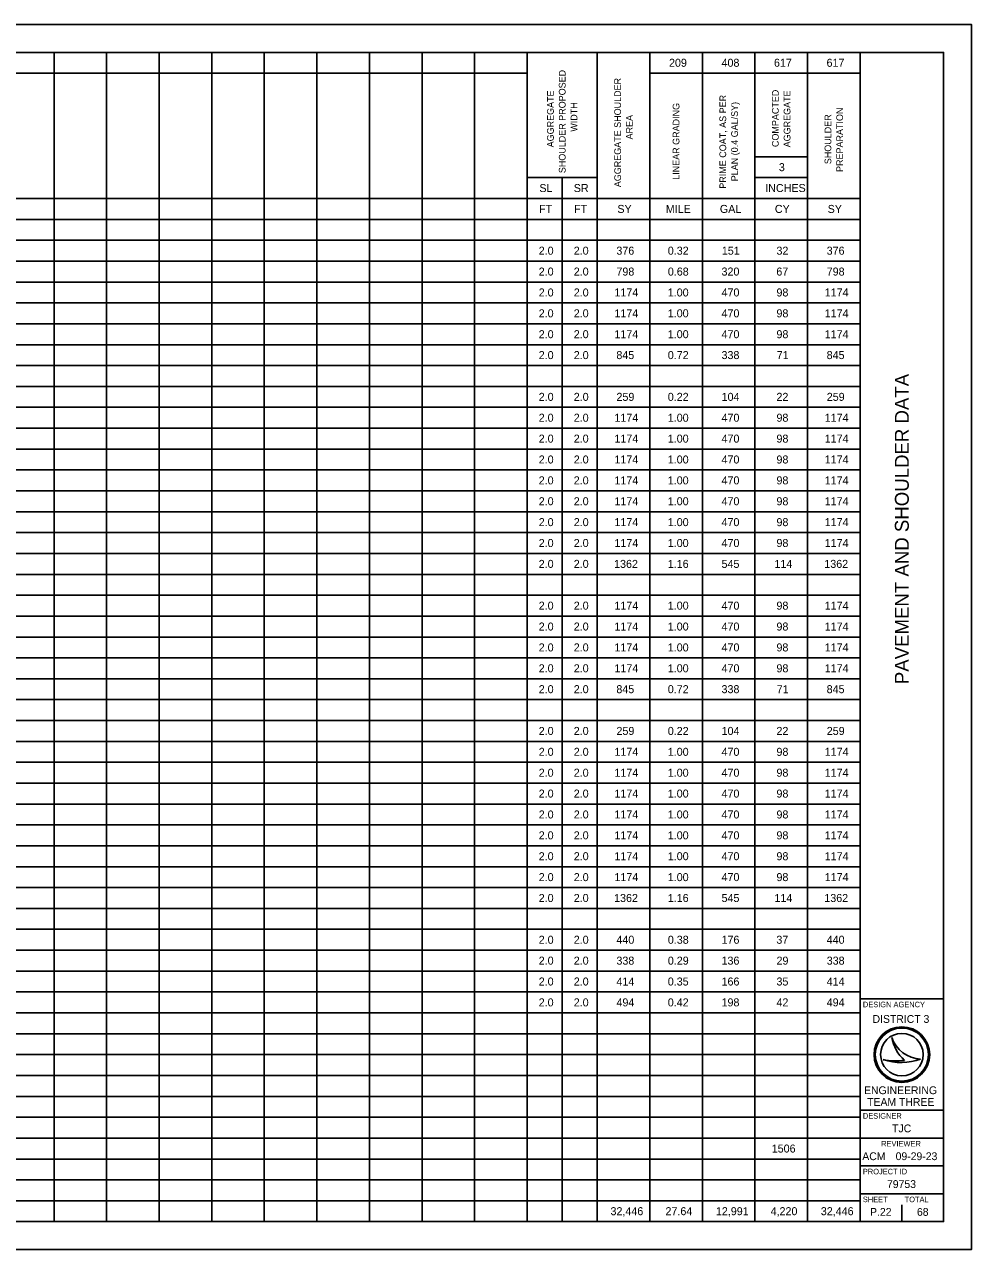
# Model space of a CAD drawing. Extents: x 0 to 34, y 0 to 22.
# Drawn here: x 17 to 34, y 0 to 22 of the extents above; entities that cross this region are included whole.
import ezdxf

# ---------------------------------------------------------------- set-up
doc = ezdxf.new("R2010")
doc.units = 0
for name, color, linetype in [('SH_Border', 7, 'Continuous'), ('SH_Cut_Line', 7, 'Continuous'), ('SH_Data', 7, 'Continuous'), ('SH_Text', 7, 'Continuous')]:
    doc.layers.add(name, color=color, linetype=linetype)

msp = doc.modelspace()

# ---------------------------------------------------------------- linework, layer by layer
at = {"layer": 'SH_Border'}
for p, q in [((32, 0.5), (32, 21.5)), ((32, 4.5), (33.5, 4.5)), ((32, 2.5), (33.5, 2.5)), ((32, 2), (33.5, 2)), ((32, 1.5), (33.5, 1.5)), ((32, 1), (33.5, 1))]:
    msp.add_line(p, q, dxfattribs=at)
msp.add_lwpolyline([(1.5, 21.5), (33.5, 21.5), (33.5, 0.5), (1.5, 0.5)], close=True, dxfattribs=at)
at = {"layer": 'SH_Cut_Line'}
msp.add_lwpolyline([(0, 0), (34, 0), (34, 22), (0, 22)], close=True, dxfattribs=at)
at = {"layer": 'SH_Data'}
for p, q in [((32.567, 3.81), (32.567, 3.81)), ((32.417, 3.41), (32.417, 3.41)), ((32.75, 3.5), (32.75, 3.5)), ((33.087, 3.419), (33.087, 3.419)), ((32.375, 0.675), (32.375, 0.675)), ((32.75, 0.5), (32.75, 0.8))]:
    msp.add_line(p, q, dxfattribs=at)
for radius in [0.5, 0.477, 0.477, 0.382]:
    msp.add_circle((32.75, 3.5), radius, dxfattribs=at)
for centre, radius, start, end in [((33.116, 3.998), 0.58, 198.9257, 198.9319), ((33.347, 3.97), 0.796, 191.6379, 191.6421), ((33.116, 3.998), 0.58, 198.9319, 267.1657), ((33.347, 3.97), 0.796, 191.6421, 226.0947), ((32.739, 4.37), 1.013, 251.4576, 290.0832), ((32.648, 4.654), 1.266, 259.4964, 259.4995), ((32.739, 4.37), 1.013, 251.4527, 251.4576), ((32.648, 4.654), 1.266, 259.4995, 276.6672)]:
    msp.add_arc(centre, radius, start, end, dxfattribs=at)
at = {"layer": 'SH_Text'}
for p, q in [((1.5, 21.5), (32, 21.5)), ((17.53, 21.5), (17.53, 0.5)), ((18.474, 21.5), (18.474, 0.5)), ((19.417, 21.5), (19.417, 0.5)), ((20.361, 21.5), (20.361, 0.5)), ((21.305, 21.5), (21.305, 0.5)), ((22.248, 21.5), (22.248, 0.5)), ((23.192, 21.5), (23.192, 0.5)), ((24.136, 21.5), (24.136, 0.5)), ((25.08, 21.5), (25.08, 0.5)), ((26.023, 21.5), (26.023, 0.5)), ((27.281, 21.5), (27.281, 0.5)), ((28.225, 21.5), (28.225, 0.5)), ((29.169, 21.5), (29.169, 0.5)), ((30.113, 21.5), (30.113, 0.5)), ((31.056, 21.5), (31.056, 0.5)), ((32, 21.5), (32, 0.5)), ((10.164, 21.125), (26.023, 21.125)), ((28.225, 21.125), (32, 21.125)), ((30.113, 19.625), (31.056, 19.625)), ((26.023, 19.25), (27.281, 19.25)), ((26.652, 19.25), (26.652, 0.5)), ((30.113, 19.25), (31.056, 19.25)), ((9.22, 18.875), (32, 18.875)), ((1.5, 18.5), (32, 18.5)), ((1.5, 18.125), (32, 18.125)), ((1.5, 17.75), (32, 17.75)), ((1.5, 17.375), (32, 17.375)), ((1.5, 17), (32, 17)), ((1.5, 16.625), (32, 16.625)), ((1.5, 16.25), (32, 16.25)), ((1.5, 15.875), (32, 15.875)), ((1.5, 15.5), (32, 15.5)), ((1.5, 15.125), (32, 15.125)), ((1.5, 14.75), (32, 14.75)), ((1.5, 14.375), (32, 14.375)), ((1.5, 14), (32, 14)), ((1.5, 13.625), (32, 13.625)), ((1.5, 13.25), (32, 13.25)), ((1.5, 12.875), (32, 12.875)), ((1.5, 12.5), (32, 12.5)), ((1.5, 12.125), (32, 12.125)), ((1.5, 11.75), (32, 11.75)), ((1.5, 11.375), (32, 11.375)), ((1.5, 11), (32, 11)), ((1.5, 10.625), (32, 10.625)), ((1.5, 10.25), (32, 10.25)), ((1.5, 9.875), (32, 9.875)), ((1.5, 9.5), (32, 9.5)), ((1.5, 9.125), (32, 9.125)), ((1.5, 8.75), (32, 8.75)), ((1.5, 8.375), (32, 8.375)), ((1.5, 8), (32, 8)), ((1.5, 7.625), (32, 7.625)), ((1.5, 7.25), (32, 7.25)), ((1.5, 6.875), (32, 6.875)), ((1.5, 6.5), (32, 6.5)), ((1.5, 6.125), (32, 6.125)), ((1.5, 5.75), (32, 5.75)), ((1.5, 5.375), (32, 5.375)), ((1.5, 5), (32, 5)), ((1.5, 4.625), (32, 4.625)), ((1.5, 4.25), (32, 4.25)), ((1.5, 3.875), (32, 3.875)), ((1.5, 3.5), (32, 3.5)), ((1.5, 3.125), (32, 3.125)), ((1.5, 2.75), (32, 2.75)), ((1.5, 2.375), (32, 2.375)), ((1.5, 2), (32, 2)), ((1.5, 1.625), (32, 1.625)), ((1.5, 1.25), (32, 1.25)), ((1.5, 0.875), (32, 0.875)), ((1.5, 0.5), (32, 0.5))]:
    msp.add_line(p, q, dxfattribs=at)

# ---------------------------------------------------------------- texts
at = {"layer": 'SH_Data'}
msp.add_text('PAVEMENT AND SHOULDER DATA', height=0.25, rotation=90, dxfattribs=at).set_placement((32.875, 10.153))
for s, height, p in [('DESIGN AGENCY', 0.1, (32.05, 4.35)), ('DISTRICT 3', 0.14, (32.224, 4.07)), ('ENGINEERING', 0.14, (32.071, 2.79)), ('TEAM THREE', 0.14, (32.127, 2.58)), ('DESIGNER', 0.1, (32.05, 2.35)), ('TJC', 0.14, (32.575, 2.105)), ('REVIEWER', 0.1, (32.378, 1.85)), ('ACM', 0.14, (32.04, 1.605)), ('09-29-23', 0.14, (32.638, 1.605)), ('PROJECT ID', 0.1, (32.05, 1.35)), ('79753', 0.14, (32.483, 1.105)), ('SHEET', 0.1, (32.05, 0.85)), ('TOTAL', 0.1, (32.8, 0.85)), ('P.22', 0.14, (32.179, 0.605)), ('68', 0.14, (33.021, 0.605))]:
    msp.add_text(s, height=height, dxfattribs=at).set_placement(p)
at = {"layer": 'SH_Text'}
for s, height, p in [('209', 0.1438, (28.57, 21.241)), ('408', 0.1438, (29.513, 21.241)), ('617', 0.1438, (30.454, 21.241)), ('617', 0.1438, (31.398, 21.241)), ('3', 0.144, (30.542, 19.366)), ('SL', 0.1438, (26.243, 18.991)), ('SR', 0.1438, (26.86, 18.991)), ('INCHES', 0.1438, (30.297, 18.991)), ('FT', 0.1438, (26.238, 18.616)), ('FT', 0.1438, (26.867, 18.616)), ('SY', 0.1438, (27.643, 18.616)), ('MILE', 0.1438, (28.512, 18.616)), ('GAL', 0.1438, (29.483, 18.616)), ('CY', 0.1438, (30.47, 18.616)), ('SY', 0.1438, (31.418, 18.616)), ('2.0', 0.1438, (26.231, 17.866)), ('2.0', 0.1438, (26.86, 17.866)), ('376', 0.1438, (27.625, 17.866)), ('0.32', 0.1438, (28.548, 17.866)), ('151', 0.1438, (29.518, 17.866)), ('32', 0.1438, (30.499, 17.866)), ('376', 0.1438, (31.4, 17.866)), ('2.0', 0.1438, (26.231, 17.491)), ('2.0', 0.1438, (26.86, 17.491)), ('798', 0.1438, (27.626, 17.491)), ('0.68', 0.1438, (28.549, 17.491)), ('320', 0.1438, (29.513, 17.491)), ('67', 0.1438, (30.497, 17.491)), ('798', 0.1438, (31.401, 17.491)), ('2.0', 0.1438, (26.231, 17.116)), ('2.0', 0.1438, (26.86, 17.116)), ('1174', 0.1438, (27.59, 17.116)), ('1.00', 0.1438, (28.548, 17.116)), ('470', 0.1438, (29.513, 17.116)), ('98', 0.1438, (30.499, 17.116)), ('1174', 0.1438, (31.365, 17.116)), ('2.0', 0.1438, (26.231, 16.741)), ('2.0', 0.1438, (26.86, 16.741)), ('1174', 0.1438, (27.59, 16.741)), ('1.00', 0.1438, (28.548, 16.741)), ('470', 0.1438, (29.513, 16.741)), ('98', 0.1438, (30.499, 16.741)), ('1174', 0.1438, (31.365, 16.741)), ('2.0', 0.1438, (26.231, 16.366)), ('2.0', 0.1438, (26.86, 16.366)), ('1174', 0.1438, (27.59, 16.366)), ('1.00', 0.1438, (28.548, 16.366)), ('470', 0.1438, (29.513, 16.366)), ('98', 0.1438, (30.499, 16.366)), ('1174', 0.1438, (31.365, 16.366)), ('2.0', 0.1438, (26.231, 15.991)), ('2.0', 0.1438, (26.86, 15.991)), ('845', 0.1438, (27.625, 15.991)), ('0.72', 0.1438, (28.548, 15.991)), ('338', 0.1438, (29.513, 15.991)), ('71', 0.1438, (30.504, 15.991)), ('845', 0.1438, (31.4, 15.991)), ('2.0', 0.1438, (26.231, 15.241)), ('2.0', 0.1438, (26.86, 15.241)), ('259', 0.1438, (27.627, 15.241)), ('0.22', 0.1438, (28.548, 15.241)), ('104', 0.1438, (29.514, 15.241)), ('22', 0.1438, (30.499, 15.241)), ('259', 0.1438, (31.402, 15.241)), ('2.0', 0.1438, (26.231, 14.866)), ('2.0', 0.1438, (26.86, 14.866)), ('1174', 0.1438, (27.59, 14.866)), ('1.00', 0.1438, (28.548, 14.866)), ('470', 0.1438, (29.513, 14.866)), ('98', 0.1438, (30.499, 14.866)), ('1174', 0.1438, (31.365, 14.866)), ('2.0', 0.1438, (26.231, 14.491)), ('2.0', 0.1438, (26.86, 14.491)), ('1174', 0.1438, (27.59, 14.491)), ('1.00', 0.1438, (28.548, 14.491)), ('470', 0.1438, (29.513, 14.491)), ('98', 0.1438, (30.499, 14.491)), ('1174', 0.1438, (31.365, 14.491)), ('2.0', 0.1438, (26.231, 14.116)), ('2.0', 0.1438, (26.86, 14.116)), ('1174', 0.1438, (27.59, 14.116)), ('1.00', 0.1438, (28.548, 14.116)), ('470', 0.1438, (29.513, 14.116)), ('98', 0.1438, (30.499, 14.116)), ('1174', 0.1438, (31.365, 14.116)), ('2.0', 0.1438, (26.231, 13.741)), ('2.0', 0.1438, (26.86, 13.741)), ('1174', 0.1438, (27.59, 13.741)), ('1.00', 0.1438, (28.548, 13.741)), ('470', 0.1438, (29.513, 13.741)), ('98', 0.1438, (30.499, 13.741)), ('1174', 0.1438, (31.365, 13.741)), ('2.0', 0.1438, (26.231, 13.366)), ('2.0', 0.1438, (26.86, 13.366)), ('1174', 0.1438, (27.59, 13.366)), ('1.00', 0.1438, (28.548, 13.366)), ('470', 0.1438, (29.513, 13.366)), ('98', 0.1438, (30.499, 13.366)), ('1174', 0.1438, (31.365, 13.366)), ('2.0', 0.1438, (26.231, 12.991)), ('2.0', 0.1438, (26.86, 12.991)), ('1174', 0.1438, (27.59, 12.991)), ('1.00', 0.1438, (28.548, 12.991)), ('470', 0.1438, (29.513, 12.991)), ('98', 0.1438, (30.499, 12.991)), ('1174', 0.1438, (31.365, 12.991)), ('2.0', 0.1438, (26.231, 12.616)), ('2.0', 0.1438, (26.86, 12.616)), ('1.00', 0.1438, (28.548, 12.616)), ('470', 0.1438, (29.513, 12.616)), ('98', 0.1438, (30.499, 12.616)), ('1174', 0.1438, (27.59, 12.616)), ('1174', 0.1438, (31.365, 12.616)), ('2.0', 0.1438, (26.231, 12.241)), ('2.0', 0.1438, (26.86, 12.241)), ('1362', 0.1438, (27.584, 12.241)), ('1.16', 0.1438, (28.548, 12.241)), ('545', 0.1438, (29.513, 12.241)), ('114', 0.1438, (30.463, 12.241)), ('1362', 0.1438, (31.358, 12.241)), ('2.0', 0.1438, (26.231, 11.491)), ('2.0', 0.1438, (26.86, 11.491)), ('1174', 0.1438, (27.59, 11.491)), ('1.00', 0.1438, (28.548, 11.491)), ('470', 0.1438, (29.513, 11.491)), ('98', 0.1438, (30.499, 11.491)), ('1174', 0.1438, (31.365, 11.491)), ('2.0', 0.1438, (26.231, 11.116)), ('2.0', 0.1438, (26.86, 11.116)), ('1174', 0.1438, (27.59, 11.116)), ('1.00', 0.1438, (28.548, 11.116)), ('470', 0.1438, (29.513, 11.116)), ('98', 0.1438, (30.499, 11.116)), ('1174', 0.1438, (31.365, 11.116)), ('2.0', 0.1438, (26.231, 10.741)), ('2.0', 0.1438, (26.86, 10.741)), ('1174', 0.1438, (27.59, 10.741)), ('1.00', 0.1438, (28.548, 10.741)), ('470', 0.1438, (29.513, 10.741)), ('98', 0.1438, (30.499, 10.741)), ('1174', 0.1438, (31.365, 10.741)), ('2.0', 0.1438, (26.231, 10.366)), ('2.0', 0.1438, (26.86, 10.366)), ('1174', 0.1438, (27.59, 10.366)), ('1.00', 0.1438, (28.548, 10.366)), ('470', 0.1438, (29.513, 10.366)), ('98', 0.1438, (30.499, 10.366)), ('1174', 0.1438, (31.365, 10.366)), ('2.0', 0.1438, (26.231, 9.991)), ('2.0', 0.1438, (26.86, 9.991)), ('845', 0.1438, (27.625, 9.991)), ('0.72', 0.1438, (28.548, 9.991)), ('338', 0.1438, (29.513, 9.991)), ('71', 0.1438, (30.504, 9.991)), ('845', 0.1438, (31.4, 9.991)), ('2.0', 0.1438, (26.231, 9.241)), ('2.0', 0.1438, (26.86, 9.241)), ('259', 0.1438, (27.627, 9.241)), ('0.22', 0.1438, (28.548, 9.241)), ('104', 0.1438, (29.514, 9.241)), ('22', 0.1438, (30.499, 9.241)), ('259', 0.1438, (31.402, 9.241)), ('2.0', 0.1438, (26.231, 8.866)), ('2.0', 0.1438, (26.86, 8.866)), ('1174', 0.1438, (27.59, 8.866)), ('1.00', 0.1438, (28.548, 8.866)), ('470', 0.1438, (29.513, 8.866)), ('98', 0.1438, (30.499, 8.866)), ('1174', 0.1438, (31.365, 8.866)), ('2.0', 0.1438, (26.231, 8.491)), ('2.0', 0.1438, (26.86, 8.491)), ('1174', 0.1438, (27.59, 8.491)), ('1.00', 0.1438, (28.548, 8.491)), ('470', 0.1438, (29.513, 8.491)), ('98', 0.1438, (30.499, 8.491)), ('1174', 0.1438, (31.365, 8.491)), ('2.0', 0.1438, (26.231, 8.116)), ('2.0', 0.1438, (26.86, 8.116)), ('1174', 0.1438, (27.59, 8.116)), ('1.00', 0.1438, (28.548, 8.116)), ('470', 0.1438, (29.513, 8.116)), ('98', 0.1438, (30.499, 8.116)), ('1174', 0.1438, (31.365, 8.116)), ('2.0', 0.1438, (26.231, 7.741)), ('2.0', 0.1438, (26.86, 7.741)), ('1174', 0.1438, (27.59, 7.741)), ('1.00', 0.1438, (28.548, 7.741)), ('470', 0.1438, (29.513, 7.741)), ('98', 0.1438, (30.499, 7.741)), ('1174', 0.1438, (31.365, 7.741)), ('2.0', 0.1438, (26.231, 7.366)), ('2.0', 0.1438, (26.86, 7.366)), ('1174', 0.1438, (27.59, 7.366)), ('1.00', 0.1438, (28.548, 7.366)), ('470', 0.1438, (29.513, 7.366)), ('98', 0.1438, (30.499, 7.366)), ('1174', 0.1438, (31.365, 7.366)), ('2.0', 0.1438, (26.231, 6.991)), ('2.0', 0.1438, (26.86, 6.991)), ('1174', 0.1438, (27.59, 6.991)), ('1.00', 0.1438, (28.548, 6.991)), ('470', 0.1438, (29.513, 6.991)), ('98', 0.1438, (30.499, 6.991)), ('1174', 0.1438, (31.365, 6.991)), ('2.0', 0.1438, (26.231, 6.616)), ('2.0', 0.1438, (26.86, 6.616)), ('1174', 0.1438, (27.59, 6.616)), ('1.00', 0.1438, (28.548, 6.616)), ('470', 0.1438, (29.513, 6.616)), ('98', 0.1438, (30.499, 6.616)), ('1174', 0.1438, (31.365, 6.616)), ('2.0', 0.1438, (26.231, 6.241)), ('2.0', 0.1438, (26.86, 6.241)), ('1362', 0.1438, (27.584, 6.241)), ('1.16', 0.1438, (28.548, 6.241)), ('545', 0.1438, (29.513, 6.241)), ('114', 0.1438, (30.463, 6.241)), ('1362', 0.1438, (31.358, 6.241)), ('2.0', 0.1438, (26.231, 5.491)), ('2.0', 0.1438, (26.86, 5.491)), ('440', 0.1438, (27.626, 5.491)), ('0.38', 0.1438, (28.549, 5.491)), ('176', 0.1438, (29.513, 5.491)), ('37', 0.1438, (30.497, 5.491)), ('440', 0.1438, (31.401, 5.491)), ('2.0', 0.1438, (26.231, 5.116)), ('2.0', 0.1438, (26.86, 5.116)), ('338', 0.1438, (27.626, 5.116)), ('0.29', 0.1438, (28.549, 5.116)), ('136', 0.1438, (29.513, 5.116)), ('29', 0.1438, (30.5, 5.116)), ('338', 0.1438, (31.401, 5.116)), ('2.0', 0.1438, (26.231, 4.741)), ('2.0', 0.1438, (26.86, 4.741)), ('414', 0.1438, (27.627, 4.741)), ('0.35', 0.1438, (28.548, 4.741)), ('166', 0.1438, (29.513, 4.741)), ('35', 0.1438, (30.499, 4.741)), ('414', 0.1438, (31.401, 4.741)), ('2.0', 0.1438, (26.231, 4.366)), ('2.0', 0.1438, (26.86, 4.366)), ('494', 0.1438, (27.627, 4.366)), ('0.42', 0.1438, (28.548, 4.366)), ('198', 0.1438, (29.513, 4.366)), ('42', 0.1438, (30.499, 4.366)), ('494', 0.1438, (31.401, 4.366)), ('1506', 0.1438, (30.414, 1.741)), ('32,446', 0.1438, (27.52, 0.616)), ('27.64', 0.1438, (28.507, 0.616)), ('12,991', 0.1438, (29.412, 0.616)), ('4,220', 0.1438, (30.394, 0.616)), ('32,446', 0.1438, (31.295, 0.616))]:
    msp.add_text(s, height=height, dxfattribs=at).set_placement(p)
for s, height, p in [('SHOULDER PROPOSED ', 0.12058, (26.713, 19.33)), ('AGGREGATE SHOULDER ', 0.12058, (27.708, 19.078)), ('AGGREGATE ', 0.1206, (26.502, 19.794)), ('PRIME COAT, AS PER ', 0.12058, (29.596, 19.051)), ('COMPACTED ', 0.1206, (30.539, 19.799)), ('AGGREGATE', 0.1206, (30.75, 19.794)), ('WIDTH', 0.1206, (26.924, 20.075)), ('LINEAR GRADING', 0.12058, (28.757, 19.211)), ('PLAN (0.4 GAL/SY)', 0.12058, (29.807, 19.185)), ('PREPARATION', 0.12058, (31.694, 19.352)), ('AREA', 0.1206, (27.919, 19.936)), ('SHOULDER ', 0.1206, (31.483, 19.491))]:
    msp.add_text(s, height=height, rotation=90, dxfattribs=at).set_placement(p)

doc.saveas('drawing.dxf')
